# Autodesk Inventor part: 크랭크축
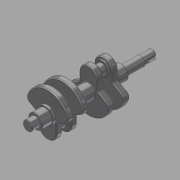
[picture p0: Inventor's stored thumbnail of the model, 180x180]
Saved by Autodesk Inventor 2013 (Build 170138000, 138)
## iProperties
Created: 2017-03
Part Number: 크랭크축
Material: 강철, 탄소
Document SubType Name: Modeling
Designer: mduedu
Density: 7.87 g/cm^3
Mass: 2638.48 g
Surface Area: 631.346 cm^2
Volume: 335.258 cm^3
Author: mduedu
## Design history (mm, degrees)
sketch "스케치1" dims "d5" = 65
  geometry: L1 (-19, 26.368)-(-19, 8.368); L2 (-19, 8.368)-(-44.545, -6.381); L3 (19, 26.368)-(19, 8.368); L4 (0, 26.368)-(0, -45); L5 (19, 8.368)-(44.545, -6.381); C1 r 10 at (0, 0); C2 r 17.5 at (0, 0); A1 r 45 centre (0, 0) between (-44.545, -6.381) and (0, -45); A2 r 45 centre (0, 0) between (0, -45) and (44.545, -6.381); A3 r 19 centre (0, 26.368) between (19, 26.368) and (0, 45.368); A4 r 19 centre (0, 26.368) between (0, 45.368) and (-19, 26.368); 3 further points
  constraints: 10 end point, 8 point on circle, 6 centre point, 5 coincident, 3 symmetric about line, 2 point on line, 1 parallel, 1 tangent, 1 vertical, 1 vertical alignment, 5 other
  dimensions: "d0" = 20 diameter of C1; "d1" = 35 diameter of C2; "d2" = 18 distance of L1.start L1.end; "d3" = 120 deg angle of L2 L1; "d4" = 45 radius of A1; "d6" = 19 radius of A4
extrude "돌출1" new body sketch "스케치1" distance "d7" = 12; taper "d8" = 0 deg
extrude "돌출2" join sketch "스케치1" distance "d9" = 5; taper "d10" = 0 deg
extrude "돌출3" join sketch "스케치1" distance "d11" = 90; taper "d12" = 0 deg
sketch "스케치2"
  geometry: C1 r 15 at (0, 26.368); C2 r 10 at (0, 26.368); A1 r 19 centre (0, 26.368) between (19, 26.368) and (-19, 26.368) reference; 1 further point
  constraints: 2 centre point, 2 coincident
  dimensions: "d13" = 30 diameter of C1; "d14" = 20 diameter of C2
extrude "돌출4" join sketch "스케치2" distance "d15" = 3; taper "d16" = 0 deg
extrude "돌출5" join sketch "스케치2" distance "d17" = 16; taper "d18" = 0 deg
fillet "모깎기1" dims "d19" = 3, "d20" = 10
fillet "모깎기2" dims "d21" = 2
sketch "스케치3"
  geometry: C1 r 15 at (0, 0); 1 further point
  constraints: 1 centre point, 1 coincident
  dimensions: "d22" = 30 diameter of C1
extrude "돌출6" join sketch "스케치3" distance "d23" = 21; taper "d24" = 0 deg
sketch "스케치4"
  geometry: C1 r 10 at (0, 0) reference; C2 r 9 at (0, 0); 1 further point
  constraints: 1 centre point
  dimensions: "d25" = 1 radial gap between concentric circles of C1 C2
extrude "돌출7" cut sketch "스케치4" distance "d26" = 25; taper "d27" = 0 deg
node "작업 평면1"
sketch "스케치5"
  geometry: L1 (-9, 0)-(9, 0) reference; L2 (-3, 0)-(3, 0); L3 (3, 0)-(3, 15); L4 (-3, 15)-(-3, 0); A1 r 3 centre (0, 15) between (3, 15) and (-3, 15); 1 further point
  constraints: 6 end point, 2 point on circle, 2 tangent, 1 centre point, 1 horizontal, 1 parallel, 1 perpendicular, 1 point on line, 1 vertical alignment
  dimensions: "d28" = 6 distance between parallel lines of L3 L4; "d30" = 18 dimension on A1 L1
extrude "돌출8" cut sketch "스케치5" distance "d31" = 3.5; taper "d32" = 0 deg
chamfer "모따기1" distance "d33" = 1; stored, may be unused: second distance "d34" = 2, angle "d35" = 45 deg
chamfer "모따기2" distance "d36" = 1; stored, may be unused: second distance "d37" = 2, angle "d38" = 45 deg
node "작업 평면2"
sketch "스케치6"
  geometry: C1 r 15 at (0, 0) reference; C2 r 15 at (0, 0) reference; 1 further point
extrude "돌출9" join sketch "스케치6" distance "d39" = 42; taper "d40" = 0 deg
sketch "스케치7" dims "d46" = 65
  geometry: L1 (-19, -26.368)-(-19, -8.368); L2 (19, -26.368)-(19, -8.368); L3 (-19, -8.368)-(-44.545, 6.381); L4 (19, -8.368)-(44.545, 6.381); L5 (0, -26.368)-(0, 45); C1 r 17.5 at (0, 0); C2 r 10 at (0, 0); A1 r 19 centre (0, -26.368) between (0, -45.368) and (19, -26.368); A2 r 19 centre (0, -26.368) between (-19, -26.368) and (0, -45.368); A3 r 45 centre (0, 0) between (0, 45) and (-44.545, 6.381); A4 r 45 centre (0, 0) between (44.545, 6.381) and (0, 45); 3 further points
  constraints: 10 end point, 8 point on circle, 6 centre point, 5 coincident, 3 symmetric about line, 2 point on line, 1 parallel, 1 tangent, 1 vertical, 5 other
  dimensions: "d41" = 20 diameter of C2; "d42" = 35 diameter of C1; "d43" = 18 distance of L2.start L2.end; "d44" = 120 deg angle of L4 L2; "d45" = 45 radius of A4; "d47" = 19 radius of A1
extrude "돌출10" join sketch "스케치7" distance "d48" = 12; taper "d49" = 0 deg
sketch "스케치8"
  geometry: C1 r 15 at (0, -26.368); C2 r 10 at (0, -26.368); A1 r 19 centre (0, -26.368) between (-19, -26.368) and (19, -26.368) reference; 1 further point
  constraints: 2 centre point, 2 coincident
  dimensions: "d50" = 30 diameter of C1; "d51" = 20 diameter of C2
extrude "돌출11" join sketch "스케치8" distance "d52" = 3; taper "d53" = 0 deg
extrude "돌출12" join sketch "스케치8" distance "d54" = 16; taper "d55" = 0 deg
fillet "모깎기3" dims "d56" = 3, "d57" = 10
fillet "모깎기4" dims "d58" = 2
chamfer "모따기3" distance "d59" = 1; stored, may be unused: second distance "d60" = 2, angle "d61" = 45 deg
node "작업 평면3"
fillet "모깎기5" dims "d62" = 1
sketch "스케치9"
  geometry: C1 r 17.5 at (0, 0) reference; 1 further point
extrude "돌출13" join sketch "스케치9" distance "d63" = 5; taper "d64" = 0 deg
sketch "스케치10"
  geometry: C1 r 10 at (0, 0) reference; 1 further point
extrude "돌출14" join sketch "스케치10" distance "d65" = 36; taper "d66" = 0 deg
sketch "스케치11"
  geometry: C1 r 15 at (0, 0); 1 further point
  constraints: 1 centre point, 1 coincident
  dimensions: "d67" = 30 diameter of C1
extrude "돌출15" join sketch "스케치11" distance "d68" = 20; taper "d69" = 0 deg
chamfer "모따기4" distance "d70" = 1; stored, may be unused: second distance "d71" = 2, angle "d72" = 45 deg
node "솔리드1"
mirror "대칭1"
mirror "대칭2"
node "투영된 루프1"
